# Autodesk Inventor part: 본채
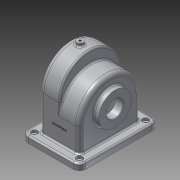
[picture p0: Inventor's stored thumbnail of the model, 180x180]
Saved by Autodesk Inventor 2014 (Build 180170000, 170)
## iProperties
Created: 2017-11
Part Number: 본채
Material: 알루미늄 6061
Document SubType Name: Modeling
Designer: user
Density: 2.71 g/cm^3
Appearance: 알루미늄 - 평지
Mass: 1015.85 g
Surface Area: 1181.14 cm^2
Volume: 374.854 cm^3
Author: user
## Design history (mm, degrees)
sketch "스케치2"
  geometry: L1 (-55, 75)-(55, 75); L2 (55, 75)-(55, -75); L3 (55, -75)-(-55, -75); L4 (-55, -75)-(-55, 75); L5 (-55, 75)-(55, -75); L6 (55, 75)-(-55, -75); 1 further point
  constraints: 12 end point, 2 midpoint, 2 parallel, 1 horizontal, 1 perpendicular
  dimensions: "d5" = 110 distance of L1.start L1.end; "d6" = 150 distance of L1.end L2.end
extrude "돌출1" new body sketch "스케치2" distance "d7" = 12; taper "d8" = 0 deg
sketch "스케치3"
  geometry: L1 (-75, 12)-(75, 12) reference; L2 (-58, 80)-(-58, 12); L3 (58, 80)-(58, 12); L4 (-58, 12)-(58, 12); L5 (75, 0)-(-75, 0) reference; A1 r 58 centre (0, 80) between (58, 80) and (-58, 80); 3 further points
  constraints: 6 end point, 3 perpendicular, 3 point on circle, 2 horizontal alignment, 2 point on line, 2 tangent, 2 vertical alignment, 1 centre point, 1 midpoint
  dimensions: "d9" = 58 radius of A1; "d11" = 80 distance from line of L5 L2.start
extrude "돌출2" new body sketch "스케치3" distance "d12" = 38; taper "d13" = 0 deg
sketch "스케치4"
  geometry: L1 (-80, -58)-(-12, -58) reference; L2 (-12, 58)-(-80, 58) reference; L3 (0, 75)-(0, -75) reference; L4 (-57, -58)-(-12, -58); L5 (-57, 58)-(-12, 58); L6 (-12, 58)-(-12, -58); A1 r 58 centre (-80, 0) between (-80, 58) and (-80, -58) reference; A2 r 58 centre (-57, 0) between (-57, 58) and (-57, -58)
  constraints: 6 end point, 2 point on circle, 2 vertical alignment, 1 centre point, 1 perpendicular, 1 point on line, 1 tangent
  dimensions: "d18" = 57 distance from line of L3 A2.centre; "d19" = 58 radius of A2
extrude "돌출3" join sketch "스케치4" distance "d20" = 38; taper "d21" = 0 deg
feature "쉘1" dims "d22" = 5
sketch "스케치6"
  geometry: L1 (-33, 53)-(33, 53) reference; L2 (-33, -53)-(-33, 53) reference; L3 (33, 53)-(33, -53) reference; L4 (33, -53)-(-33, -53) reference; 1 further point
extrude "돌출4" cut sketch "스케치6" stored distance "d23" = 38; taper "d24" = 0 deg
feature "결합1"
  node "솔리드1"
sketch "스케치7"
  geometry: L1 (0, -75)-(0, 75) reference; C1 r 37.5 at (65, 0); 1 further point
  constraints: 1 centre point, 1 horizontal alignment, 1 midpoint
  dimensions: "d27" = 75 diameter of C1; "d28" = 65 distance from line of L1 C1.centre
extrude "돌출5" join sketch "스케치7" distance "d29" = 9; taper "d30" = 0 deg
sketch "스케치8"
  geometry: L1 (0, 75)-(0, -75) reference; C1 r 31 at (-65, 0); 1 further point
  constraints: 1 centre point, 1 horizontal alignment, 1 midpoint
  dimensions: "d31" = 62 diameter of C1; "d32" = 65 distance from line of L1 C1.centre
extrude "돌출6" join sketch "스케치8" distance "d33" = 10; taper "d34" = 0 deg
sketch "스케치9"
  geometry: C1 r 37.5 at (0, 0) reference; 1 further point
hole "구멍1" sketch "스케치9" at (0, 0) diameter "d35" = 32; stored, may be unused: countersink angle "d39" = 90 deg, drill point angle "d41" = 118 deg; dims "d36" = 6, "d37" = 4, "d38" = 2, "d40" = 8
sketch "스케치10" dims "d42" = 58
  geometry: C1 r 16 at (0, 0) reference; C2 r 37.5 at (0, 0) reference; 3 further points
  constraints: 2 horizontal alignment, 1 coincident, 2 other
hole "구멍2" sketch "스케치10" at (29, 0) diameter "d43" = 2.459; stored, may be unused: countersink angle "d47" = 90 deg, drill point angle "d49" = 118 deg; dims "d44" = 6, "d45" = 4, "d46" = 2, "d48" = 8
sketch "스케치11" dims "d53" = 52
  geometry: C1 r 16 at (0, 0) reference; C2 r 31 at (0, 0) reference; 3 further points
  constraints: 2 vertical alignment, 1 coincident, 2 other
hole "구멍3" sketch "스케치11" at (0, 26) diameter "d54" = 2.459; stored, may be unused: countersink angle "d58" = 90 deg, drill point angle "d60" = 118 deg; dims "d55" = 6, "d56" = 4, "d57" = 2, "d59" = 8
node "작업 평면1"
sketch "스케치12"
  geometry: L1 (93, -133)-(93, -17) reference; C1 r 6 at (74, -75); 1 further point
  constraints: 1 centre point, 1 horizontal alignment
  dimensions: "d65" = 12 diameter of C1; "d66" = 19 distance from line of L1 C1.centre
extrude "돌출7" join sketch "스케치12" stored distance "d67" = 9; taper "d68" = 0 deg
sketch "스케치13"
  geometry: C1 r 6 at (0, 0) reference; 1 further point
hole "구멍4" sketch "스케치13" at (0, 0) diameter "d69" = 4.459; stored, may be unused: countersink angle "d73" = 90 deg, drill point angle "d75" = 118 deg; dims "d70" = 20, "d71" = 4, "d72" = 2, "d74" = 8
fillet "모깎기1" dims "d76" = 12
sketch "스케치14"
  geometry: A1 r 12 centre (86, -12) between (98, -12) and (86, 0) reference; A2 r 12 centre (0, -12) between (0, 0) and (-12, -12) reference; A3 r 12 centre (0, -138) between (-12, -138) and (0, -150) reference; A4 r 12 centre (86, -138) between (86, -150) and (98, -138) reference; 1 further point
hole "구멍5" sketch "스케치14" at (0, -12), (0, -138), (86, -12), (86, -138) diameter "d77" = 5; stored, may be unused: countersink angle "d81" = 90 deg, drill point angle "d83" = 118 deg; dims "d78" = 6, "d79" = 12, "d80" = 5, "d82" = 8
fillet "모깎기2" dims "d84" = 3
chamfer "모따기1" distance "d85" = 1; stored, may be unused: second distance "d86" = 2, angle "d87" = 45 deg
chamfer "모따기2" distance "d88" = 1; stored, may be unused: second distance "d89" = 2, angle "d90" = 45 deg
fillet "모깎기3" dims "d91" = 8
fillet "모깎기4" dims "d92" = 3
fillet "모깎기5" dims "d93" = 3
fillet "모깎기6" dims "d94" = 3
sketch "스케치15"
  geometry: L1 (73, -15)-(-13, -15) reference; L2 (68, 0)-(68, 42) reference; 2 further points
  constraints: 1 other
  dimensions: "d95" = 40 distance from line of L1 point (30, 25); "d96" = 38 distance from line of L2 point (30, 25)
feature "엠보싱1" sketch "스케치15" dims "d5" = 110, "d6" = 150, "d97" = 0.5, "d98" = 0
fillet "모깎기7" dims "d99" = 3
pattern_circular "원형 패턴1" dims angle "d51" = 360 deg
pattern_circular "원형 패턴2" dims angle "d62" = 360 deg
node "솔리드2"
other parameters: "d64" = -144
